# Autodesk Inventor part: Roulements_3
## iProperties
Created: 2002-06
Part Number: Roulements_3
Material: Par défaut
Document SubType Name: Modélisation
Designer: REVEST Pierre
Control State: 0
Master: False
Checked Out: False
Shininess: 20.0
Length Units: 11269
Angle Units: 11279
Time Units: 11290
Mass Units: 11283
Length Display Precision: 3
Angle Display Precision: 2
Density: 0.0
Volumn: 0.0
Area: 0.0
PropertySet Name: Model Information
Author: REVEST Pierre
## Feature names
1. Base1
